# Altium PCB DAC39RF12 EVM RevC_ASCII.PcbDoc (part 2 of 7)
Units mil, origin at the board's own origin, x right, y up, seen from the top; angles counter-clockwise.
Board outline 5071.81 x 2716.54 mil, 16 copper layers (Top Layer, L2 GND1, L3 PWR1, L4 GND2, L5 PWR2, L6 GND3, L7 Ctrl Signal 1, L8 GND4, L9 GND5, L10 Ctrl Signal 2, L11 GND6, L12 PWR3, L13 GND7, L14 PWR4, L15 GND8, Bottom Layer), stack 82.4 mil thick; 596 components, 375 nets, 3310 pads, 1662 vias.
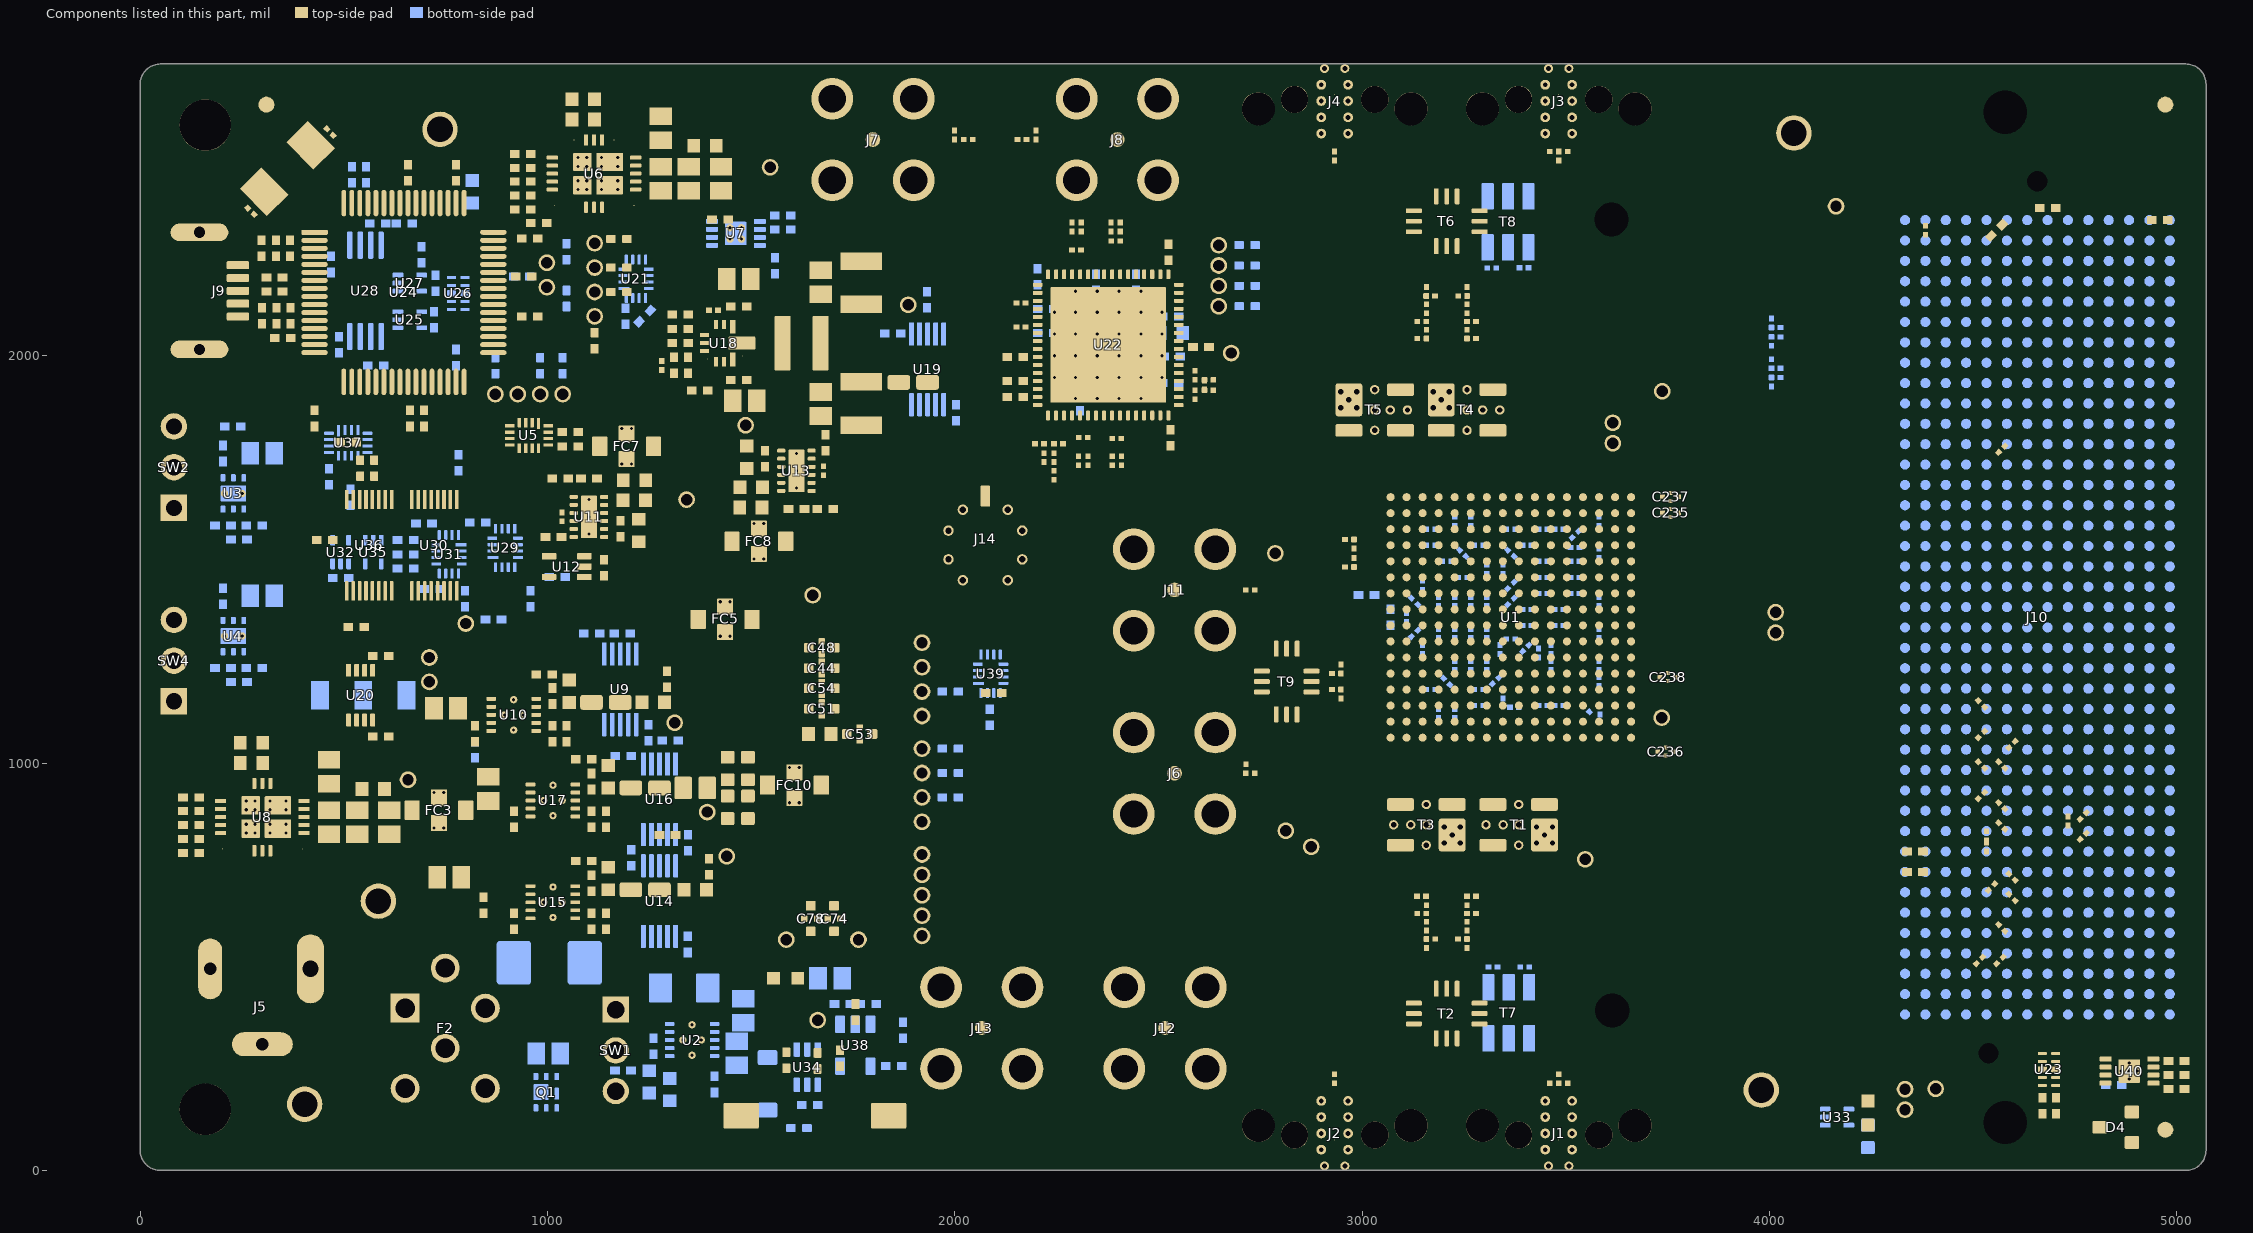
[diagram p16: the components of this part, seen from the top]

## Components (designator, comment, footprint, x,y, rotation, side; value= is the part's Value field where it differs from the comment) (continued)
C65 "C1005X5R1A225K050BC" 0402L_cap 1533.96,1747.33 r270 top
C66 "GRM033R61A105ME44D" 0201_cap#1 1677.76,1717.81 r270 top
C67 "0603ZD106KAT2A" 0603L_cap#1 1499.51,1627.77 r0 top
C68 "GRM155R61E104KA87D" 0402L#1 1423.77,2334.95 r180 top
C69 "GRM155R61E104KA87D" 0402L#1 1191.41,2097.15 r90 bottom
C70 "GRM155R61E104KA87D" 0402L#1 1238.85,2097.29 r45 bottom
C71 "0603ZD106KAT2A" 0603L_cap#1 1500.49,1677.45 r0 top
C72 "GRM155R61E104KA87D" 0402L#1 1344.42,554.91 r270 bottom
C73 "GRM155R61E104KA87D" 0402L#1 4703.69,159.33 r270 top
C74 "NFM18PC105R0J3D" NFM18PC 1703.55,618.42 r270 top
C75 "0603ZD106KAT2A" 0603L_cap#1 1149.61,716.77 r270 top
C76 "C1005X5R1E105K050BC" 0402L_cap 1396.1,745.89 r270 top
C77 "GRM033Z71C104KE14D" 0201_cap#3 2623.73,1915.48 r180 top
C78 "NFM18PC105R0J3D" NFM18PC 1646.35,618.42 r270 top
C79 "C1005X5R1A475K050BE" 0402L_cap 1143.61,612.01 r90 top
C80 "GRM155R61E104KA87D" 0402L#1 1344.45,804.91 r270 bottom
C81 "GRM033Z71C104KE14D" 0201_cap#3 2623.73,1941.17 r180 top
C82 "0603ZD106KAT2A" 0603L_cap#1 1149.61,966.77 r270 top
C83 "GRM188R60J476ME15D" 0603L_cap#2 1442.17,986.77 r270 top
C84 "GRM155R61E104KA87D" 0402L#1 2085.82,1112.49 r90 bottom
C85 "C1005X5R1A475K050BE" 0402L_cap 1143.61,862.01 r90 top
C86 "08053D106KAT4A" 0805L_cap 1469.78,2188.58 r180 top
C87 "08053D106KAT4A" 0805L_cap 1484.62,1889.53 r180 top
C88 "04023D104KAT2A" 0402L_cap 1469.78,2121.53 r180 top
C89 "04023D104KAT2A" 0402L_cap 1469.78,1940.83 r180 top
C90 "GRM033Z71C104KE14D" 0201_cap#1 1407.65,2111.94 r180 top
C91 "C2012X7S1A226M125AC" 0805L_cap 1670.46,1881.65 r90 top
C92 "C2012X7S1A226M125AC" 0805L_cap 1670.46,2180.71 r270 top
C93 "1210YD476KAT2A" 1210L_cap 1770.46,2179.33 r270 top
C94 "1210YD476KAT2A" 1210L_cap 1770.46,1883.03 r90 top
C95 "GRM155R61E104KA87D" 0402L#1 2002.44,1860.49 r270 bottom
C96 "C1005X5R1A225K050BC" 0402L_cap 1373.99,1915.42 r0 top
C97 "GRM155R61E104KA87D" 0402L#1 1055.77,1812.47 r180 top
C98 "GRM155R61E104KA87D" 0402L#1 1055.77,1777.47 r180 top
C99 "0201BB104KW160" 0201_cap#1 2725.49,975.31 r180 top
C100 "0201BB104KW160" 0201_cap#1 2947.76,1169.6 r90 top
C101 "0201BB104KW160" 0201_cap#1 2714.47,986.33 r270 top
C102 "0201BB104KW160" 0201_cap#1 2936.74,1180.62 r180 top
C103 "0201BB104KW160" 0201_cap#1 2936.74,1219.99 r180 top
C104 "0201BB104KW160" 0201_cap#1 2947.76,1231.02 r270 top
C105 "0201BB104KW160" 0201_cap#1 2725.49,1425.31 r180 top
C106 "GRM033Z71C104KE14D" 0201_cap#1 2219.07,1750.05 r90 top
C107 "GRM033Z71C104KE14D" 0201_cap#1 2243.6,1750.05 r90 top
C108 "GRM155R61E104KA87D" 0402L#1 2095.82,1172.18 r0 top
C109 "GRM188R60J476ME15D" 0603L_cap#2 1442.17,891.65 r90 top
C110 "GRM188R60J476ME15D" 0603L_cap#2 1492.17,986.77 r270 top
C111 "GRM188R60J476ME15D" 0603L_cap#2 1492.17,891.65 r90 top
C115 "GRM155R61E104KA87D" 0402L#1 2524.11,2254.66 r270 top
C116 "GRM155R61E104KA87D" 0402L#1 2445.37,2180.29 r90 bottom
C117 "GRM155R61E104KA87D" 0402L#1 2346.95,2180.29 r90 bottom
C118 "GRM155R61E104KA87D" 0402L#1 2203.25,2194.07 r270 bottom
C119 "GRM155R61E104KA87D" 0402L#1 2222.93,2115.33 r180 bottom
C120 "GRM155R61E104KA87D" 0402L#1 2222.93,2056.28 r180 bottom
C121 "GRM155R61E104KA87D" 0402L#1 2148.56,1997.22 r0 top
C122 "GRM155R61E104KA87D" 0402L#1 2148.56,1938.17 r0 top
C123 "GRM155R61E104KA87D" 0402L#1 2148.56,1898.8 r0 top
C124 "GRM155R61E104KA87D" 0402L#1 2307.58,1885.02 r270 bottom
C125 "GRM155R61E104KA87D" 0402L#1 2529.03,1798.84 r90 top
C126 "GRM155R61E104KA87D" 0402L#1 2604.39,2021.28 r180 top
C127 "GRM033Z71C104KE14D" 0201_cap#1 2162.22,2070.96 r0 top
C128 "GRM033Z71C104KE14D" 0201_cap#1 2162.22,2130.02 r0 top
C131 "GRM033Z71C104KE14D" 0201_cap#1 2406.14,2316 r270 top
C132 "GRM033Z71C104KE14D" 0201_cap#1 2383.19,2316 r270 top
C133 "GRM033Z71C104KE14D" 0201_cap#1 2310.47,2316 r270 top
C134 "GRM033Z71C104KE14D" 0201_cap#1 2287.29,2316 r270 top
C137 "GRM033Z71C104KE14D" 0201_cap#1 2303.91,1742.5 r90 top
C138 "GRM033Z71C104KE14D" 0201_cap#1 2326.87,1742.5 r90 top
C139 "GRM033Z71C104KE14D" 0201_cap#1 2386.71,1742.5 r90 top
C140 "GRM033Z71C104KE14D" 0201_cap#1 2409.66,1742.5 r90 top
C144 "C1608X5R1A106K080AC" 0603L_cap#1 2532.14,2055.96 r0 bottom
C145 "GRM155R61E104KA87D" 0402L#1 2530.02,2096.65 r0 bottom
C146 "04026D475KAT2A" 0402L_cap 369.53,2098.23 r90 top
C147 "04023D104KAT2A" 0402L_cap 334.53,2098.23 r90 top
C148 "04023D104KAT2A" 0402L_cap 657.49,2449.65 r270 top
C149 "04023D104KAT2A" 0402L_cap 775.6,2449.65 r270 top
C150 "04023D104KAT2A" 0402L_cap 578.75,1975.99 r180 bottom
C151 "04023D104KAT2A" 0402L_cap 936.82,2195.01 r180 bottom
C152 "04023D104KAT2A" 0402L_cap 775.6,1995.68 r270 bottom
C153 "04026D475KAT2A" 0402L_cap 368.16,2263.75 r270 top
C154 "04023D104KAT2A" 0402L_cap 333.16,2263.75 r270 top
C155 "GRM155R61E104KA87D" 0402L#1 941.82,2195.01 r0 top
C158 "04023D104KAT2A" 0402L_cap 487.77,2027.53 r90 bottom
C159 "GJM0336C1E180JB01J" 0201_cap#1 272.06,2355.03 r135 top
C160 "GJM0336C1E180JB01J" 0201_cap#1 466.2,2549.17 r135 top
C161 "GRM155R61E104KA87D" 0402L#1 958.05,1403.19 r270 bottom
C162 "GRM155R61E104KA87D" 0402L#1 867.57,1353.03 r0 bottom
C163 "GRM155R61E104KA87D" 0402L#1 798.05,1403.19 r90 bottom
C164 "GRM155R61E104KA87D" 0402L#1 829.24,1590.72 r0 bottom
C165 "GRM155R61E104KA87D" 0402L#1 696.86,1588.38 r0 bottom
C167 "GRM155R61E104KA87D" 0402L#1 516.29,1652.55 r90 bottom
C168 "GRM155R61E104KA87D" 0402L#1 511.13,1787.79 r0 top
C169 "GRM155R61E104KA87D" 0402L#1 463.71,1703.11 r90 bottom
C170 "GRM155R61E104KA87D" 0402L#1 1755.73,388.93 r90 top
C171 "GRM155R61E104KA87D" 0402L#1 1718.33,275.94 r270 top
C172 "GRM033Z71C104KE14D" 0201_cap#1 3109.18,1357.79 r270 bottom
C173 "GRM033Z71C104KE14D" 0201_cap#1 3373.74,1137.25 r0 bottom
C174 "GRM033Z71C104KE14D" 0201_cap#1 3550.04,1133.46 r135 bottom
C175 "GRM033Z71C104KE14D" 0201_cap#1 3432.74,1270.39 r270 bottom
C176 "GRM033Z71C104KE14D" 0201_cap#1 3463.51,1279.05 r90 bottom
C177 "GRM033Z71C104KE14D" 0201_cap#1 3404.45,1377.47 r0 bottom
C178 "GRM033Z71C104KE14D" 0201_cap#1 3443.82,1495.58 r0 bottom
C179 "GRM033Z71C104KE14D" 0201_cap#1 3345.4,1475.9 r270 bottom
C180 "GRM033Z71C104KE14D" 0201_cap#1 3581.62,1515.27 r90 bottom
C181 "GRM033Z71C104KE14D" 0201_cap#1 3523.45,1561.53 r45 bottom
C182 "GRM033Z71C104KE14D" 0201_cap#1 3443.82,1574.32 r180 bottom
C183 "GRM033Z71C104KE14D" 0201_cap#1 3338.4,1279.05 r270 bottom
C184 "GRM033Z71C104KE14D" 0201_cap#1 3365.08,1304.73 r0 bottom
C185 "GRM033Z71C104KE14D" 0201_cap#1 3483.19,1377.47 r0 bottom
C186 "GRM033Z71C104KE14D" 0201_cap#1 3443.82,1416.84 r0 bottom
C187 "GRM033Z71C104KE14D" 0201_cap#1 3365.08,1397.16 r45 bottom
C188 "GRM033Z71C104KE14D" 0201_cap#1 3365.08,1515.27 r315 bottom
C189 "GRM033Z71C104KE14D" 0201_cap#1 3581.62,1318.42 r270 bottom
C190 "GRM033Z71C104KE14D" 0201_cap#1 3581.62,1239.68 r90 bottom
C191 "GRM033Z71C104KE14D" 0201_cap#1 3483.19,1141.25 r0 bottom
C192 "GRM033Z71C104KE14D" 0201_cap#1 3581.62,1397.16 r90 bottom
C193 "GRM033Z71C104KE14D" 0201_cap#1 3443.82,1141.25 r180 bottom
C194 "GRM033Z71C104KE14D" 0201_cap#1 3583.62,1130.23 r90 bottom
C195 "GRM033Z71C104KE14D" 0201_cap#1 3581.62,1200.31 r270 bottom
C196 "GRM033Z71C104KE14D" 0201_cap#1 3168.23,1574.32 r180 bottom
C197 "GRM033Z71C104KE14D" 0201_cap#1 3168.23,1534.95 r180 bottom
C198 "GRM033Z71C104KE14D" 0201_cap#1 3246.97,1515.27 r315 bottom
C199 "GRM033Z71C104KE14D" 0201_cap#1 3286.34,1534.95 r0 bottom
C200 "GRM033Z71C104KE14D" 0201_cap#1 3266.66,1594.01 r90 bottom
C201 "GRM033Z71C104KE14D" 0201_cap#1 3227.29,1594.01 r90 bottom
C202 "GRM033Z71C104KE14D" 0201_cap#1 3227.29,1239.68 r270 bottom
C203 "GRM033Z71C104KE14D" 0201_cap#1 3266.66,1239.68 r90 bottom
C204 "GRM033Z71C104KE14D" 0201_cap#1 3266.66,1318.42 r90 bottom
C205 "GRM033Z71C104KE14D" 0201_cap#1 3266.66,1397.16 r270 bottom
C206 "GRM033Z71C104KE14D" 0201_cap#1 3246.97,1456.21 r0 bottom
C207 "GRM033Z71C104KE14D" 0201_cap#1 3207.6,1495.58 r0 bottom
C208 "GRM033Z71C104KE14D" 0201_cap#1 3227.29,1318.42 r90 bottom
C209 "GRM033Z71C104KE14D" 0201_cap#1 3187.92,1318.42 r90 bottom
C210 "GRM033Z71C104KE14D" 0201_cap#1 3401.56,1282.16 r225 bottom
C211 "GRM033Z71C104KE14D" 0201_cap#1 3404.45,1338.1 r0 bottom
C212 "GRM033Z71C104KE14D" 0201_cap#1 3483.19,1338.1 r0 bottom
C213 "GRM033Z71C104KE14D" 0201_cap#1 3443.82,1456.21 r180 bottom
C214 "GRM033Z71C104KE14D" 0201_cap#1 3365.08,1436.53 r45 bottom
C215 "GRM033Z71C104KE14D" 0201_cap#1 3404.45,1534.95 r0 bottom
C216 "GRM033Z71C104KE14D" 0201_cap#1 3581.62,1594.01 r270 bottom
C217 "GRM033Z71C104KE14D" 0201_cap#1 3483.19,1574.32 r0 bottom
C218 "GRM033Z71C104KE14D" 0201_cap#1 3365.08,1574.32 r0 bottom
C219 "GRM033Z71C104KE14D" 0201_cap#1 3187.92,1121.57 r270 bottom
C220 "GRM033Z71C104KE14D" 0201_cap#1 3207.6,1200.31 r135 bottom
C221 "GRM033Z71C104KE14D" 0201_cap#1 3168.23,1180.62 r180 bottom
C222 "GRM033Z71C104KE14D" 0201_cap#1 3227.29,1121.57 r270 bottom
C223 "GRM033Z71C104KE14D" 0201_cap#1 3286.34,1141.25 r0 bottom
C224 "GRM033Z71C104KE14D" 0201_cap#1 3286.34,1180.62 r0 bottom
C225 "GRM033Z71C104KE14D" 0201_cap#1 3306.03,1239.68 r90 bottom
C226 "GRM033Z71C104KE14D" 0201_cap#1 3306.03,1318.42 r90 bottom
C227 "GRM033Z71C104KE14D" 0201_cap#1 3306.03,1397.16 r270 bottom
C228 "GRM033Z71C104KE14D" 0201_cap#1 3306.03,1475.9 r270 bottom
C229 "GRM033Z71C104KE14D" 0201_cap#1 3227.29,1397.16 r270 bottom
C230 "GRM033Z71C104KE14D" 0201_cap#1 3187.92,1397.16 r270 bottom
C231 "GRM033Z71C104KE14D" 0201_cap#1 3148.55,1279.05 r90 bottom
C232 "GRM033Z71C104KE14D" 0201_cap#1 3128.86,1318.42 r45 bottom
C233 "GRM033Z71C104KE14D" 0201_cap#1 3128.86,1397.16 r315 bottom
C234 "GRM033Z71C104KE14D" 0201_cap#1 3148.55,1436.53 r270 bottom
C235 "NFM15PC474R0J3D" NFM15PC 3757.18,1614.22 r180 top
C236 "NFM15PC474R0J3D" NFM15PC 3745.31,1028.04 r180 top
C237 "NFM15PC474R0J3D" NFM15PC 3757.18,1653.9 r180 top
C238 "NFM15PC474R0J3D" NFM15PC 3750.61,1211.1 r180 top
C239 "GRM033Z71C104KE14D" 0201_cap#1 3345.4,1169.6 r90 bottom
C240 "GRM033Z71C104KE14D" 0201_cap#1 3327.71,1202.31 r45 bottom
C241 "GRM033Z71C104KE14D" 0201_cap#1 3522.56,1495.58 r0 bottom
C242 "GRM033Z71C104KE14D" 0201_cap#1 3522.56,1416.84 r0 bottom
C243 "GRM033Z71C104KE14D" 0201_cap#1 3522.56,1456.21 r0 bottom
C244 "GRM033Z71C104KE14D" 0201_cap#1 3522.56,1529.45 r0 bottom
C245 "GRM155R61E104KA87D" 0402L#1 4844.92,209.51 r180 bottom
D1 "MBR130T1G" SOD-123 1540.24,212.76 r270 bottom
D2 "SMBJ15CA" SMBJ15CA 1004.55,510 r0 bottom
D3 "LTST-C191TGKT" LED_LTST-C190-Green 1584.78,471.85 r0 top
D4 "SDM40E20LC-7" SOT-323-DIO 4850.34,106.08 r180 top
D5 "LTST-C191TGKT" LED_LTST-C190-Green 4241.78,140.84 r90 top
F1 "SF-1206FP250-2" SF-1206F500M-2_1206 1335.43,448.25 r180 bottom
F2 "BNX002-11" FIL_BNX002-11 749.06,300.06 r90 top
FB1 "BLE18PS080SN1D" 0603L#1 1386.69,2516.13 r0 top
FB2 "BLE18PS080SN1D" 0603L#1 572.33,936.49 r0 top
FB3 "BLE18PS080SN1D" 0603L#1 1259.67,1149.17 r0 top
FB4 "BLE18PS080SN1D" 0603L#1 1668.65,1071.46 r0 top
FB5 "BLE18PS080SN1D" 0603L#1 1362.64,689.21 r0 top
FB6 "BLM21SP471SN1D" 0805L#1 1362.64,939.21 r0 top
FB7 "NFZ15SG151SN11D" 0402L#1 299.53,2098.23 r90 top
FB8 "NFZ15SG151SN11D" 0402L#1 298.16,2263.75 r270 top
FC3 "FeedThruCap" NFM31PC#1 733.64,884.41 r0 top
FC5 "FeedThruCap" NFM31PC#2 1436.08,1352.91 r0 top
FC7 "FeedThruCap" NFM31PC#1 1194.46,1777.79 r0 top
FC8 "FeedThruCap" NFM31PC#1 1518.84,1544.65 r180 top
FC10 "FeedThruCap" NFM31PC#1 1606.14,946.1 r0 top
FID1 "Fiducial Mark" Fiducial10-20 4971.81,100 r0 top
FID2 "Fiducial Mark" Fiducial10-20 4971.81,2616.54 r90 top
FID3 "Fiducial Mark" Fiducial10-20 310,2616.54 r90 top
H3 "2069-440-SS" FP-2116-440-AL_STANDOFF_HEX_1-4-MFG 160,2566.54 r0 top locked
H4 "2069-440-SS" FP-2116-440-AL_STANDOFF_HEX_1-4-MFG 160,150 r0 top
H5 "Balun-Shield" Balun-Shield 3360,386.83 r180 bottom
H6 "Balun-Shield" Balun-Shield 3358.16,2328.74 r180 bottom
J1 "HK-LR-SR2(11)" HiRose-HK-LR-SR2-SWM1092-04A-MicroStirp-6mil-Female-Backdrill 3482.6,0 r90 top
J2 "HK-LR-SR2(11)" HiRose-HK-LR-SR2-SWM1092-04A-MicroStirp-6mil-Female-Backdrill 2932.6,0 r90 top
J3 "HK-LR-SR2(11)" HiRose-HK-LR-SR2-SWM1092-04A-MicroStirp-6mil-Female-Backdrill 3482.6,2716.53 r270 top
J4 "HK-LR-SR2(11)" HiRose-HK-LR-SR2-SWM1092-04A-MicroStirp-6mil-Female-Backdrill 2932.6,2716.53 r270 top
J5 "RAPC722X" RAPC722X -140.83,495.04 r0 top
J6 "132134-15" FP-132134-15_CONN_SMA_JACK-MFG#1 2539.47,975.31 r270 top
J7 "132134-15" FP-132134-15_CONN_SMA_JACK-MFG#1 1799.06,2530.98 r0 top
J8 "132134-15" FP-132134-15_CONN_SMA_JACK-MFG#1 2399.06,2530.98 r90 top
J9 "UX60SC-MB-5S8" Hirose_UX60SC-MB-5S8 0,2159.42 r0 top
J10 "ASP-184330-01" Samtec_ASP-184330-01 4657.81,1358.06 r90 top locked
J11 "132134-15" FP-132134-15_CONN_SMA_JACK-MFG#1 2539.47,1425.31 r270 top
J12 "132134-15" FP-132134-15_CONN_SMA_JACK-MFG#2 2516.35,349.76 r90 top
J13 "132134-15" FP-132134-15_CONN_SMA_JACK-MFG#2 2066.35,349.76 r90 top
J14 "0853050232" Molex_0853050232 2075,1655.63 r0 top
L1 "XGL4020-152MEC" XGL4020 1623.81,2031.18 r0 top
LBL1 "THT-14-423-10" Label_650x200 4915.43,1876.87 r90 top
Logo1 "FDL Logo" FDL_Small 1192.35,1313.11 r0 top
LOGO2 "CAUTION HOT SURFACE" IEC_HotSurface_Small 3490,1815 r0 top
Logo3 "FCC disclaimer" FCC_disclaimer_stacked 4325,2325 r90 bottom
Logo4 "ESD Overlay" ESD_Overlay_Small 3785,1355 r0 top
Logo5 "WEEE" WEEE_Minimum 2810,1755 r180 bottom
LOGO6 "CE Mark" CE_Mark_5mm 2930,2430 r180 bottom
Logo7 "Texas Instruments" TI_Stacked_Overlay_Small 4205,2168.58 r0 top
MP1 "ATS-54170R-C1-R0" "DAC39 - ATS-54170R-C1-R0_BGA_HEATSINK_17p0x17p0mm" 3365.08,1357.79 r90 top
MP5 "Fan" "DAC39R - F17HA-05HC_FAN_17p0x17p0mm" 3700.08,1357.79 r0 top
PP1 "Probe Point" ProbePoint_TH_40mil 4015,1320.51 r0 top
PP2 "Probe Point" ProbePoint_TH_40mil 4015,1370.51 r0 top
PP3 "Probe Point" ProbePoint_TH_40mil 1546.48,2462.66 r0 top
PP4 "Probe Point" ProbePoint_TH_40mil 657.7,959.41 r0 top
PP5 "Probe Point" ProbePoint_TH_40mil 1312.22,1099.17 r0 top
PP6 "Probe Point" ProbePoint_TH_40mil 2812.76,834.2 r0 top
PP7 "Probe Point" ProbePoint_TH_40mil 3615.6,1835.45 r0 top
PP8 "Probe Point" ProbePoint_TH_40mil 3735.49,1111.72 r0 top
PP9 "Probe Point" ProbePoint_TH_40mil 2787.07,1514.97 r0 top
PP10 "Probe Point" ProbePoint_TH_40mil 3615.6,1785.45 r0 top
PP11 "Probe Point" ProbePoint_TH_40mil 1486.35,1829.37 r90 top
PP12 "Probe Point" ProbePoint_TH_40mil 1341.46,1647.14 r90 top
PP13 "Probe Point" ProbePoint_TH_40mil 1440.2,771.1 r0 top
PP14 "Probe Point" ProbePoint_TH_40mil 1763.55,566.92 r0 top
PP15 "Probe Point" ProbePoint_TH_40mil 1586.35,566.92 r0 top
PP16 "Probe Point" ProbePoint_TH_40mil 1392.16,880 r90 top
PP17 "Probe Point" ProbePoint_TH_40mil 1885.57,2125.06 r0 top
PP18 "Probe Point" ProbePoint_TH_40mil 2678.46,2006.82 r90 top
PP19 "Probe Point" ProbePoint_TH_40mil 998.74,2168.58 r90 top
PP20 "Probe Point" ProbePoint_TH_40mil 998.74,2228.58 r90 top
PP21 "Probe Point" ProbePoint_TH_40mil 2647.94,2221.79 r0 top
PP22 "Probe Point" ProbePoint_TH_40mil 2647.94,2171.79 r0 top
PP23 "Probe Point" ProbePoint_TH_40mil 2647.94,2121.79 r0 top
PP24 "Probe Point" ProbePoint_TH_40mil 2647.94,2271.79 r0 top
PP25 "Probe Point" ProbePoint_TH_40mil 1919.48,1175.8 r0 top
PP26 "Probe Point" ProbePoint_TH_40mil 1919.48,775.8 r90 top
PP27 "Probe Point" ProbePoint_TH_40mil 1919.48,675.8 r0 top
PP28 "Probe Point" ProbePoint_TH_40mil 1919.48,575.8 r0 top
PP29 "Probe Point" ProbePoint_TH_40mil 1919.48,725.8 r0 top
PP30 "Probe Point" ProbePoint_TH_40mil 1919.48,1235.8 r0 top
PP31 "Probe Point" ProbePoint_TH_40mil 1919.48,625.8 r90 top
PP32 "Probe Point" ProbePoint_TH_40mil 799.59,1342.79 r0 top
PP33 "Probe Point" ProbePoint_TH_40mil 1919.48,1115.8 r0 top
PP34 "Probe Point" ProbePoint_TH_40mil 1919.48,1295.8 r0 top
PP35 "Probe Point" ProbePoint_TH_40mil 1651.17,1412.58 r0 top
PP36 "Probe Point" ProbePoint_TH_40mil 1919.48,1035.8 r270 top
PP37 "Probe Point" ProbePoint_TH_40mil 1919.48,975.8 r270 top
PP38 "Probe Point" ProbePoint_TH_40mil 1919.48,915.8 r0 top
PP39 "Probe Point" ProbePoint_TH_40mil 1919.48,855.8 r0 top
PP40 "Probe Point" ProbePoint_TH_40mil 1663.3,369.24 r90 top
PP41 "Probe Point" ProbePoint_TH_40mil 3547.64,763.72 r90 top
PP42 "Probe Point" ProbePoint_TH_40mil 3736.83,1913.06 r90 top
PP43 "Probe Point" ProbePoint_TH_40mil 2874.85,794.47 r0 top
PP44 "Probe Point" ProbePoint_TH_40mil 1037.24,1906.09 r90 top
PP45 "Probe Point" ProbePoint_TH_40mil 982.24,1906.09 r90 top
PP46 "Probe Point" ProbePoint_TH_40mil 927.24,1906.09 r90 top
PP47 "Probe Point" ProbePoint_TH_40mil 872.24,1906.09 r90 top
PP48 "Probe Point" ProbePoint_TH_40mil 4332.81,199.51 r0 top
PP49 "Probe Point" ProbePoint_TH_40mil 4332.81,149.51 r0 top
PP50 "Probe Point" ProbePoint_TH_40mil 4163.4,2367.25 r0 top
PP51 "Probe Point" ProbePoint_TH_40mil 4407.81,200.66 r90 top
PP52 "Probe Point" ProbePoint_TH_40mil 710.18,1259.36 r0 top
PP53 "Probe Point" ProbePoint_TH_40mil 710.18,1199.36 r0 top
PP54 "Probe Point" ProbePoint_TH_40mil 1115.72,2096.71 r180 top
PP55 "Probe Point" ProbePoint_TH_40mil 1115.72,2156.71 r180 top
PP56 "Probe Point" ProbePoint_TH_40mil 1115.72,2216.71 r180 top
PP57 "Probe Point" ProbePoint_TH_40mil 1115.72,2276.71 r180 top
Q1 "CSD15571Q2" DQK0006C 997.2,192.2 r270 bottom
R1 "ERJ-1GN0R00C" 0201#1 3268.63,673.35 r0 top
R2 "ERJ-1GN0R00C" 0201#1 3482.6,225.06 r90 top
R3 "ERJ-1GN0R00C" 0201#1 3257.61,662.33 r270 top
R4 "ERJ-1GN0R00C" 0201#1 3257.61,599.88 r270 top
R5 "ERJ-1GN0R00C" 0201#1 3157.6,662.33 r270 top
R6 "ERJ-1GN0R00C" 0201#1 3157.6,599.88 r270 top
R7 "ERJ-1GNF1400C" 0201#1 3146.57,631.1 r0 top
R8 "ERJ-1GNF1400C" 0201#1 3268.63,631.1 r180 top
R9 "ERJ-1GN0R00C" 0201#1 3145.79,673.35 r180 top
R10 "ERJ-1GN0R00C" 0201#1 2932.6,225.06 r270 top
R11 "ERJ-1GN0R00C" 0201#1 3268.63,2042.22 r0 top
R12 "ERJ-1GN0R00C" 0201#1 3482.6,2490.51 r270 top
R13 "ERJ-1GN0R00C" 0201#1 3257.61,2053.25 r90 top
R14 "ERJ-1GN0R00C" 0201#1 3257.61,2115.7 r90 top
R15 "ERJ-1GN0R00C" 0201#1 3157.6,2053.25 r90 top
R16 "ERJ-1GN0R00C" 0201#1 3157.6,2115.7 r90 top
R17 "ERJ-1GNF1400C" 0201#1 3146.57,2084.47 r0 top
R18 "ERJ-1GNF1400C" 0201#1 3268.63,2084.47 r180 top
R19 "ERJ-1GN0R00C" 0201#1 3146.57,2042.22 r180 top
R20 "ERJ-1GN0R00C" 0201#1 2932.6,2490.51 r90 top
R21 "ERJ-2RKF1004X" 0402L#1 1260,304.77 r90 bottom
R22 "ERJ-2RKF4532X" 0402L#1 1410.24,211.26 r90 bottom
R23 "ERJ-2RKF1623X" 0402L#1 1185.43,245 r0 bottom
R24 "ERJ-6ENF4871V" 0805L#2 1693.84,471.85 r180 bottom
R25 "RCA12060000ZSEA" 1206L 494.59,1166.72 r180 bottom
R26 "RCA12060000ZSEA" 1206L 600.88,1166.72 r0 bottom
R27 "ERJ-2RKF1002X" 0402L#1 716.7,1428.1 r180 bottom
R28 "ERJ-2RKF1002X" 0402L#1 203.38,1760.11 r90 bottom
R29 "ERJ-U02F2002X" 0402L#1 242.75,1548.65 r0 bottom
R30 "ERJ-2RKF1002X" 0402L#1 203.38,1410.11 r90 bottom
R31 "ERJ-U02F3602X" 0402L#1 242.75,1198.65 r0 bottom
R32 "ERJ-2RKF1202X" 0402L#1 203.38,1583.65 r0 bottom
R33 "ERJ-2RKF1202X" 0402L#1 203.38,1233.65 r0 bottom
R34 "ERJ-1GNF49R9C" 0201#2 1998.94,2542 r270 top
R35 "ERJ-U01J561C" 0201#1 2612.7,1928.32 r90 top
R36 "ERJ-2RKF1002X" 0402L#1 939.44,2359.63 r180 top
R37 "ERJ-1GNF2400C" 0201#1 2208.05,1784.07 r0 top
R38 "ERJ-1GNF2400C" 0201#1 2254.62,1784.07 r180 top
R39 "ERA-2AEB1542X" 0402L#1 939.44,2461.63 r180 top
R40 "ERJ-2RKF1002X" 0402L#1 978.81,2325.63 r180 top
R41 "ERJ-2RKF4222X" 0402L#1 939.44,2393.63 r0 top
R42 "ERJ-2RKF4871X" 0402L#1 939.44,2427.63 r0 top
R43 "ERJ-1GNF49R9C" 0201#2 2199.06,2542 r270 top
R44 "ERJ-2RKF49R9X" 0402L#1 956.82,2096.27 r0 top
R45 "ERJ-2RKF1002X" 0402L#1 1558.34,2220.9 r270 bottom
R46 "ERJ-2RKF1002X" 0402L#1 821.87,1032.64 r90 bottom
R47 "ERJ-2RKF1002X" 0402L#1 125.08,779.98 r180 top
R48 "ERJ-2RKF9311X" 0402L#1 125.08,881.98 r180 top
R49 "ERJ-2RKF4222X" 0402L#1 125.08,813.98 r0 top
R50 "ERJ-2RKF4871X" 0402L#1 125.08,847.98 r0 top
R51 "ERJ-2GE0R00X" 0402L#1 1183.97,1317.79 r180 bottom
R52 "ERJ-2GE0R00X" 0402L#1 1108.62,1317.79 r0 bottom
R53 "ERJ-H2RF1002X" 0402L#1 821.87,1072.01 r270 top
R54 "CSS0603FT5L00" CCS0603FLxLxx 1143.54,1149.17 r0 top
R55 "ERJ-2RKF8872X" 0402L#1 1012.11,1164.92 r270 top
R56 "ERJ-U2RD1202X" 0402L#1 1012.11,1072.01 r90 top
R57 "ERJ-2RKF1242X" 0402L#1 992.42,1217.64 r0 top
R58 "ERJ-2RKF1002X" 0402L#1 1139.34,1480.11 r270 top
R59 "ERJ-2RKF2552X" 0402L#1 1101.94,1698.85 r0 top
R60 "ERJ-2RKF1002X" 0402L#1 1014.85,1555.42 r0 top
R61 "ERJ-2RKF4992X" 0402L#1 1031.57,1698.85 r0 top
R62 "ERA-2AED101X" 0402L#1 691.13,2247.94 r90 bottom
R63 "ERJ-2RKF1002X" 0402L#1 1578.02,2344.95 r180 bottom
R64 "ERJ-2RKF2552X" 0402L#1 1611.36,1623.59 r180 top
R65 "ERJ-2RKF1002X" 0402L#1 1682.76,1786.7 r270 top
R66 "ERJ-2RKF4992X" 0402L#1 1681.73,1623.59 r180 top
R67 "ERJ-2GE0R00X" 0402L#1 1294.76,823.96 r180 top
R68 "ERJ-2GE0R00X" 0402L#1 1205.71,767.51 r270 bottom
R69 "ERJ-H2RF1002X" 0402L#1 918.37,612.01 r270 top
R70 "ERJ-2RKF1002X" 0402L#1 843.53,651.38 r90 top
R71 "CSS0603FT5L00" CCS0603FLxLxx 1240.04,689.21 r0 top
R72 "ERJ-2RKF1153X" 0402L#1 1108.61,704.92 r270 top
R73 "ERJ-2RKF6651X" 0402L#1 1108.61,612.01 r90 top
R74 "ERJ-2RKF3302X" 0402L#1 1088.92,759.61 r0 top
R75 "ERJ-2GE0R00X" 0402L#1 1301.63,1055.19 r180 bottom
R76 "ERJ-2GE0R00X" 0402L#1 1186.02,1017.82 r0 bottom
R77 "ERJ-H2RF1002X" 0402L#1 918.37,862.01 r270 top
R78 "ERJ-2RKF1002X" 0402L#1 1578.02,2310.27 r180 bottom
R79 "CSS0603FT5L00" CCS0603FLxLxx 1240.04,939.21 r0 top
R80 "ERJ-2RKF1153X" 0402L#1 1108.61,954.92 r270 top
R81 "ERJ-2RKF6651X" 0402L#1 1108.61,862.01 r90 top
R82 "ERJ-2RKF3302X" 0402L#1 1088.92,1009.61 r0 top
R83 "ERJ-2RKF1002X" 0402L#1 1325.94,2031.18 r180 top
R84 "CSS0603FT2L00" CCS0603FLxLxx 1897.64,1934.79 r180 top
R85 "ERJ-2GE0R00X" 0402L#1 1931.2,2137.29 r270 bottom
R86 "ERJ-2GE0R00X" 0402L#1 1847.51,2054.58 r0 bottom
R87 "ERJ-H2RF1002X" 0402L#1 1310.62,1976.49 r270 top
R88 "ERJ-2RKF4871X" 0402L#1 1325.94,2066.18 r0 top
R89 "ERJ-2RKF1742X" 0402L#1 1325.94,2101.18 r0 top
R90 "ERJ-H2RF1002X" 0402L#1 1344.62,1976.49 r90 top
R91 "ERJ-1GNF49R9C" 0201#1 2243.6,1707 r90 top
R92 "ERJ-1GN0R00C" 0201#1 4016.02,1969.56 r180 bottom
R93 "ERJ-1GN0R00C" 0201#1 4005,1980.58 r270 bottom
R94 "ERJ-1GN0R00C" 0201#1 4016.02,1946.56 r180 bottom
R95 "ERJ-2RKF1002X" 0402L#1 4669.81,159.33 r90 top
R96 "ERJ-1GN0R00C" 0201#1 4005,1935.53 r90 bottom
R97 "ERJ-1GN0R00C" 0201#1 4016.02,2069.56 r180 bottom
R98 "ERJ-1GN0R00C" 0201#1 4005,2080.58 r270 bottom
R99 "ERJ-1GN0R00C" 0201#1 4016.02,2046.56 r180 bottom
R100 "ERJ-1GN0R00C" 0201#1 4005,2035.53 r90 bottom
R101 "ERJ-U01J561C" 0201#1 2395.03,2281.98 r180 top
R102 "ERJ-U01J561C" 0201#1 2298.6,2259.43 r180 top
R103 "ERJ-1GNF2400C" 0201#3 2589.7,1904.46 r90 top
R104 "ERJ-1GNF2400C" 0201#3 2589.7,1952.19 r270 top
R105 "ERJ-U01J561C" 0201#1 2315.49,1799.07 r0 top
R106 "ERJ-U01J561C" 0201#1 2397.73,1796.62 r180 top
R107 "ERJ-1GN0R00C" 0201#1 2979.81,1492.74 r90 top
R108 "ERJ-1GN0R00C" 0201#1 2968.78,1481.72 r180 top
R109 "ERJ-1GN0R00C" 0201#1 2979.81,1537.79 r270 top
R110 "ERJ-1GN0R00C" 0201#1 2968.78,1548.82 r180 top
R111 "ERJ-2RKF1002X" 0402L#2 872.24,1975.77 r270 bottom
R112 "ERJ-H2RF1002X" 0402L#1 2529.96,1933.57 r0 bottom
R113 "ERJ-H2RF1002X" 0402L#1 2533.86,1998.26 r0 bottom
R114 "ERJ-2RKF49R9X" 0402L#1 428.16,1846.31 r270 top
R115 "ERJ-2RKF2201X" 0402L#1 662.86,1846.31 r90 top
R116 "ERJ-2RKF1002X" 0402L#1 721.13,2088.55 r90 bottom
R117 "ERJ-2RKF49R9X" 0402L#1 956.82,2288.12 r0 top
R118 "ERJ-2RKF1002X" 0402L#2 1046.4,2140.76 r270 bottom
R119 "ERJ-2RKF1002X" 0402L#2 1046.4,2255.87 r90 bottom
R120 "ERJ-2RKF1002X" 0402L#2 1989.17,1175.8 r180 bottom
R121 "ERJ-2RKF2201X" 0402L#1 696.86,1846.31 r90 top
R122 "ERJ-2RKF1002X" 0402L#1 725.13,2178.57 r90 bottom
R123 "ERJ-2GEJ100X" 0402L#1 349.84,2043.55 r180 top
R124 "ERJ-2GEJ100X" 0402L#1 329.84,2192.41 r0 top
R125 "ERJ-2GEJ100X" 0402L#1 329.84,2157.92 r0 top
R126 "ERJ-2GEJ123X" 0402L#1 468.16,2224.38 r270 bottom
R127 "ERJ-2GEJ103X" 0402L#1 554.38,2444.65 r90 bottom
R128 "ERJ-2GEJ103X" 0402L#1 648.13,2325.17 r0 bottom
R129 "ERJ-2GEJ103X" 0402L#1 519.69,2444.65 r90 bottom
R130 "ERJ-2GEJ222X" 0402L#1 583.76,2325.17 r180 bottom
R131 "ERJ-2RKF1002X" 0402L#2 982.24,1975.77 r270 bottom
R132 "ERJ-2RKF1002X" 0402L#2 1037.24,1975.77 r270 bottom
R133 "ERJ-2RKF1002X" 0402L#1 227.64,1826.62 r0 bottom
R134 "ERJ-2RKF49R9X" 0402L#1 781.78,1737.12 r270 bottom
R135 "ERJ-2RKF1002X" 0402L#1 492.25,1454.17 r0 bottom
R136 "ERJ-2RKF49R9X" 0402L#1 452.88,1547.44 r0 top
R137 "ERJ-2RKF49R9X" 0402L#1 651.62,1547.79 r180 bottom
R138 "ERJ-2RKF1002X" 0402L#2 1115.72,2037.03 r90 top
R139 "ERJ-2RKF1002X" 0402L#2 1175.4,2156.71 r180 top
R140 "ERJ-2RKF1002X" 0402L#1 651.62,1512.79 r0 bottom
R141 "ERJ-2RKF49R9X" 0402L#1 651.62,1477.79 r180 bottom
R142 "ERJ-2RKF49R9X" 0402L#1 530.42,1334.04 r0 top
R143 "ERJ-2GEJ104X" 0402L#1 1873.33,344.07 r90 bottom
R144 "ERJ-2RKF1002X" 0402L#1 1849.73,256.93 r180 bottom
R145 "ERJ-2GE0R00X" 0402L#1 1724.24,408.61 r180 bottom
R146 "ERJ-2GE0R00X" 0402L#1 1643.69,160.32 r180 bottom
R147 "ERJ-2GE0R00X" 0402L#1 1787.23,408.61 r0 bottom
R148 "ERJ-1GN0R00C" 0201#1 3463.51,1239.68 r270 bottom
R149 "ERJ-2RKF1001X" 0402L#1 3010.75,1412.79 r180 bottom
R150 "ERJ-2RKF3601X" 0402L#1 3069.81,1357.79 r90 bottom
R151 "ERJ-2GE0R00X" 0402L#1 4682.81,2363.06 r0 top
R152 "ERJ-1GN0R00C" 0201#1 4770.31,870.56 r45 top
R153 "ERJ-1GN0R00C" 0201#1 4732.81,858.06 r90 top
R154 "ERJ-1GN0R00C" 0201#1 4770.31,820.56 r45 top
R155 "ERJ-2GEJ101X" 0402L#1 4557.78,2308.02 r225 top
R156 "ERJ-1GN0R00C" 0201#1 4570.31,1770.56 r45 top
R157 "ERJ-2RKF1002X" 0402L#2 1175.4,2216.71 r180 top
R158 "ERJ-1GN0R00C" 0201#1 4520.31,1145.55 r315 top
R159 "ERJ-1GN0R00C" 0201#1 4520.31,1070.56 r45 top
R160 "ERJ-1GN0R00C" 0201#1 4520.31,995.56 r315 top
R161 "ERJ-1GN0R00C" 0201#1 4595.31,1045.56 r225 top
R162 "ERJ-1GN0R00C" 0201#1 4520.31,920.56 r45 top
R163 "ERJ-1GN0R00C" 0201#1 4570.31,995.56 r315 top
R164 "ERJ-1GN0R00C" 0201#1 4532.81,822.03 r90 top
R165 "ERJ-1GN0R00C" 0201#1 4570.31,895.56 r315 top
R166 "ERJ-1GN0R00C" 0201#1 4532.81,794.08 r270 top
R167 "ERJ-1GN0R00C" 0201#1 4570.31,845.56 r315 top
R168 "ERJ-1GN0R00C" 0201#1 4545.33,695.56 r225 top
R169 "ERJ-1GN0R00C" 0201#1 4595.31,720.56 r135 top
R170 "ERJ-2RKF1002X" 0402L#2 1175.4,2286.71 r180 top
R171 "ERJ-1GN0R00C" 0201#1 4595.31,670.56 r135 top
R172 "ERJ-1GN0R00C" 0201#1 4515.61,515.85 r45 top
R173 "ERJ-2RKF1002X" 0402L#1 4999.17,199.51 r180 top
R174 "ERJ-2RKF1002X" 0402L#1 4999.17,234.2 r180 top
R175 "ERJ-2RKF1002X" 0402L#1 4999.17,268.88 r180 top
R176 "ERJ-1GN0R00C" 0201#1 4570.31,595.56 r315 top
R177 "ERJ-1GN0R00C" 0201#1 4565.61,515.85 r45 top
R178 "ERJ-1GN0R00C" 0201#1 4382.81,2308.06 r90 top
R179 "ERJ-2GEJ101X" 0402L#1 4357.22,783.06 r0 top
R180 "ERJ-2GEJ101X" 0402L#1 4357.22,733.06 r0 top
R181 "ERJ-2GEJ101X" 0402L#1 4958.4,2333.06 r180 top
R182 "ERJ-2RKF1002X" 0402L#2 2717.63,2271.79 r180 bottom
R183 "ERJ-2RKF1002X" 0402L#2 2717.63,2221.79 r0 bottom
R184 "ERJ-2RKF1002X" 0402L#2 2717.63,2171.79 r0 bottom
R185 "ERJ-2RKF1002X" 0402L#2 2717.63,2121.79 r0 bottom
R186 "ERJ-2RKF1002X" 0402L#2 574.28,1724.12 r270 top
R187 "ERJ-2RKF1002X" 0402L#2 540.28,1724.12 r270 top
R188 "ERJ-2RKF1002X" 0402L#2 1989.17,1035.8 r0 bottom
R189 "ERJ-2RKF1002X" 0402L#2 1989.17,975.8 r0 bottom
R190 "ERJ-2RKF1002X" 0402L#2 1989.17,915.8 r0 bottom
R191 "ERJ-3EKF3300V" 0603L#2 4241.78,83.76 r270 bottom
R192 "ERJ-2RKF1002X" 0402L#2 1586.35,270.54 r270 top
R193 "ERJ-2RKF1002X" 0402L#2 1663.37,268.85 r270 top
R194 "ERJ-2GE0R00X" 0402L#2 1617.34,104.19 r0 bottom
SW1 "500ASSP1M2QE" 500ASSP1M2QE 1167.71,294.89 r270 top
SW2 "cmp00353" 450301014042 82.96,1726.62 r270 top
SW3 "FSMSM" FSMSM 1656.51,134.36 r180 top
SW4 "cmp00353" 450301014042 82.96,1251.62 r270 top
T1 "TCBT-123+" TCBT123 3384.37,848.59 r270 top
T2 "MTX2-183+" DG3006 3207.6,385.26 r180 top
T3 "TCBT-123+" TCBT123 3157.6,848.59 r270 top
T4 "TCBT-123+" TCBT123 3257.6,1866.99 r90 top
T5 "TCBT-123+" TCBT123 3030.83,1866.99 r90 top
T6 "MTX2-183+" DG3006 3207.6,2330.32 r0 top
T7 "TCM2-63WX+" "DB1627 No Vias" 3360,386.83 r0 bottom
T8 "TCM2-63WX+" "DB1627 No Vias" 3358.16,2328.74 r180 bottom
T9 "MTX2-133+" DG3006 2814.69,1200.31 r90 top
TP1 "5011" Keystone5011 736.23,2556.02 r0 top
TP2 "5011" Keystone5011 3980,197.51 r0 top
TP3 "5011" Keystone5011 4060,2546.95 r0 top
TP4 "5010" Keystone5010 584.9,661.2 r0 top
TP5 "5125" Keystone5125 403.94,162.71 r90 top
U1 "DAC39RF12ACK" ACK0256A 3365.08,1357.79 r180 top locked
U2 "TPS259261DRC" DRC0010J 1355.12,320.32 r0 bottom
U3 "TPS7A2501DRVR" DRV0006A 228.97,1662.04 r90 bottom
U4 "TPS7A2501DRVR" DRV0006A 228.97,1312.04 r90 bottom
U5 "SN74AVC4T774RSV" RSV0016A 954.6,1804.59 r270 top
U6 "TPSM82913RDUR" RDU0028A 1114.3,2447.32 r90 top
U7 "24LC64FT-I/MNY" TDFN8#1 1462.28,2300.42 r180 bottom
U8 "TPSM82913RDUR" RDU0028A 299.95,867.68 r90 top
U9 "INA226AIDGS" DGS0010 1178.58,1181.17 r270 bottom
U10 "TPS7A9601DSC" DRC0010J 916.99,1118.46 r0 top
U11 "LM27762DSS" DSS0012B 1101.94,1604.63 r180 top
U12 "SN74AUP1G04DCK" DCK0005A 1047.25,1482.6 r180 top
U13 "LM27762DSS" DSS0012B 1611.36,1717.81 r0 top
U14 "INA226AIDGS" DGS0010 1275.08,661.21 r270 bottom
U15 "TPS7A9601DSC" DRC0010J 1013.49,658.46 r0 top
U16 "INA226AIDGS" DGS0010 1275.08,911.21 r270 bottom
U17 "TPS7A9601DSC" DRC0010J 1013.49,908.46 r0 top
U18 "TPS543620RPYR" RPY0014A 1441.23,2031.18 r0 top
U19 "INA226AIDGS" DGS0010 1933.07,1966.79 r270 bottom
U20 "SN74AVCH2T45DCU" DCU0008A 541.24,1166.86 r270 top
U21 "SN74AVC4T774RSV" RSV0016A 1217.21,2189.08 r0 bottom
U22 "LMK04828BISQ/NOPB" NKD0064A 2376.47,2026.75 r180 top
U23 "TMUX1136DGS" DQA0010A#1 4686.25,247.98 r0 top
U24 "FT4232HL-REEL" LQFP64-MFG 647.64,2155.48 r0 top locked
U25 "SN74LVC1G125DRL" DRL0005A 661.99,2088.55 r0 bottom
U26 "TMUX1136DQA" DQA0010A#2 780.95,2153.25 r0 bottom
U27 "SN74LVC1G125DRL" DRL0005A 661.99,2178.57 r0 bottom
U28 "93LC46B-I/ST" TSSOP-8 553.16,2159.42 r270 bottom
U29 "SN74AVC4T774RSV" RSV0016A 896.08,1528.54 r0 bottom
U30 "SN74CBTLV3257DGV" DGV0016A 722.41,1535.23 r270 top
U31 "SN74AVC4T774RSV" RSV0016A 758.08,1512.79 r180 bottom
U32 "SN74LVC1G125DRL" DRL0005A 492.25,1518.3 r90 bottom
U33 "SN74LVC1G126DRL" DRL0005A 4165.87,131 r0 bottom
U34 "SN74LVC1G11DCKR" DCK0006A 1637.78,253.63 r90 bottom
U35 "SN74LVC1G125DRL" DRL0005A 572.25,1518.3 r270 bottom
U36 "SN74CBTLV3257DGV" DGV0016A 562.41,1535.23 r90 top
U37 "SN74AVC4T774RSV" RSV0016A 510.95,1786.42 r270 bottom
U38 "TPS3125G15DBVR" DBV0005A 1755.73,307.43 r270 bottom
U39 "SN74AVC4T774RSV" RSV0016A 2087.94,1219.42 r0 bottom
U40 "24LC64FT-I/MNY" TDFN8#2 4883.43,244.04 r180 top
Y1 "ABM3-12.000MHZ-D2Y-T" XTAL_ABM3 361.34,2459.89 r45 top
ZZ1 "These assemblies are ESD sensitive, ESD precautions shall be observed." AssemblyNote 100.51,13060.05 r0 top

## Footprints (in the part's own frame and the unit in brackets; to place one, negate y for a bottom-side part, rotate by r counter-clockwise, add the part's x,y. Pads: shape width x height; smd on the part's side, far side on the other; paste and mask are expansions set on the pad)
0201#1 [mm] "Data from Kemet datasheet CC101_COM dated 7/28/11"
  rect 0.36x0.32 smd mask+0: 1(-0.28,0) 2(0.28,0)
0201#2 [mm] "Data from Kemet datasheet CC101_COM dated 7/28/11"
  rect 0.36x0.32 smd mask+0.048: 1(-0.28,0) 2(0.28,0)
0201#3 [mm] "Data from Kemet datasheet CC101_COM dated 7/28/11"
  rrect20% 0.36x0.32 smd mask+0: 1(-0.28,0) 2(0.28,0)
0201_cap#1 [mm] "Data from Kemet datasheet CC101_COM dated 7/28/11"
  rect 0.36x0.32 smd mask+0: 1(-0.28,0) 2(0.28,0)
0201_cap#2 [mm] "Data from Kemet datasheet CC101_COM dated 7/28/11"
  rect 0.36x0.32 smd mask+0.048: 1(-0.28,0) 2(0.28,0)
0201_cap#3 [mm] "Data from Kemet datasheet CC101_COM dated 7/28/11"
  rrect20% 0.36x0.32 smd mask+0: 1(-0.28,0) 2(0.28,0)
0402L#1 [mm] "0402 from SM-752 data"
  rect 0.6x0.5 smd: 1(-0.5,0) 2(0.5,0)
0402L#2 [mm] "0402 from SM-752 data"
  rrect20% 0.6x0.5 smd mask+0: 1(-0.5,0) 2(0.5,0)
0402L_cap [mm] "0402 from SM-752 data"
  rect 0.6x0.5 smd: 1(-0.5,0) 2(0.5,0)
500ASSP1M2QE [mm]
  rect 1.635x1.635 hole 1.09: 1(-2.54,0)
  round 1.635 hole 1.09: 2(0,0) 3(2.54,0)
  silkscreen extent -5.08,-2.54 5.08,2.54
0603L#1 [mm] "0603 from SM-752 data"
  rect 0.8x0.85 smd: 1(-0.7,0) 2(0.7,0)
  silkscreen extent -0.07,-0.33 0.07,0.33
0603L#2 [mm] "0603 from SM-752 data"
  rrect20% 0.8x0.85 smd: 1(-0.7,0) 2(0.7,0)
  silkscreen extent -0.07,-0.33 0.07,0.33
0603L_cap#1 [mm] "0603 from SM-752 data"
  rect 0.8x0.85 smd: 1(-0.7,0) 2(0.7,0)
  silkscreen extent -0.07,-0.33 0.07,0.33
0603L_cap#2 [mm] "0603 from SM-752 data"
  rrect20% 0.8x0.85 smd: 1(-0.7,0) 2(0.7,0)
  silkscreen extent -0.07,-0.33 0.07,0.33
0805L#1 [mm] "0805 from SM-752 data"
  rrect20% 1.1x1.4 smd: 1(-0.75,0) 2(0.75,0)
0805L#2 [mm] "0805 from SM-752 data"
  rect 1.1x1.4 smd: 1(-0.75,0) 2(0.75,0)
0805L_cap [mm] "0805 from SM-752 data"
  rect 1.1x1.4 smd: 1(-0.75,0) 2(0.75,0)
1206L [mm] "1206 from SM-752 data"
  rect 1.1x1.75 smd: 1(-1.35,0) 2(1.35,0)
  silkscreen extent -0.4,-0.77 0.4,0.77
1210L_cap [mm] "1210 from SM-752 data"
  rect 1.1x2.6 smd: 1(-1.35,0) 2(1.35,0)
  silkscreen extent -0.4,-1.2 0.4,1.2
450301014042 [mm]
  round 1.65 hole 1.016: 1(0,0) 2(-2.54,0)
  rect 1.65x1.65 hole 1.016: 3(2.54,0)
  silkscreen extent -4.25,-1.3 4.25,1.3
ACK0256A [mm]
  round 0.5 smd paste+0 mask+0: A1(-7.5,7.5) A2(-6.5,7.5) A3(-5.5,7.5) A4(-4.5,7.5) A5(-3.5,7.5) A6(-2.5,7.5) A7(-1.5,7.5) A8(-0.5,7.5) A9(0.5,7.5) A10(1.5,7.5) A11(2.5,7.5) A12(3.5,7.5) A13(4.5,7.5) A14(5.5,7.5) A15(6.5,7.5) A16(7.5,7.5) B1(-7.5,6.5) B2(-6.5,6.5) B3(-5.5,6.5) B4(-4.5,6.5) B5(-3.5,6.5) B6(-2.5,6.5) B7(-1.5,6.5) B8(-0.5,6.5) B9(0.5,6.5) B10(1.5,6.5) B11(2.5,6.5) B12(3.5,6.5) B13(4.5,6.5) B14(5.5,6.5) B15(6.5,6.5) B16(7.5,6.5) C1(-7.5,5.5) C2(-6.5,5.5) C3(-5.5,5.5) C4(-4.5,5.5) C5(-3.5,5.5) C6(-2.5,5.5) C7(-1.5,5.5) C8(-0.5,5.5) C9(0.5,5.5) C10(1.5,5.5) C11(2.5,5.5) C12(3.5,5.5) C13(4.5,5.5) C14(5.5,5.5) C15(6.5,5.5) C16(7.5,5.5) D1(-7.5,4.5) D2(-6.5,4.5) D3(-5.5,4.5) D4(-4.5,4.5) D5(-3.5,4.5) D6(-2.5,4.5) D7(-1.5,4.5) D8(-0.5,4.5) D9(0.5,4.5) D10(1.5,4.5) D11(2.5,4.5) D12(3.5,4.5) D13(4.5,4.5) D14(5.5,4.5) D15(6.5,4.5) D16(7.5,4.5) E1(-7.5,3.5) E2(-6.5,3.5) E3(-5.5,3.5) E4(-4.5,3.5) E5(-3.5,3.5) E6(-2.5,3.5) E7(-1.5,3.5) E8(-0.5,3.5) E9(0.5,3.5) E10(1.5,3.5) E11(2.5,3.5) E12(3.5,3.5) E13(4.5,3.5) E14(5.5,3.5) E15(6.5,3.5) E16(7.5,3.5) F1(-7.5,2.5) F2(-6.5,2.5) F3(-5.5,2.5) F4(-4.5,2.5) F5(-3.5,2.5) F6(-2.5,2.5) F7(-1.5,2.5) F8(-0.5,2.5) F9(0.5,2.5) F10(1.5,2.5) F11(2.5,2.5) F12(3.5,2.5) F13(4.5,2.5) F14(5.5,2.5) F15(6.5,2.5) F16(7.5,2.5) G1(-7.5,1.5) G2(-6.5,1.5) G3(-5.5,1.5) G4(-4.5,1.5) G5(-3.5,1.5) G6(-2.5,1.5) G7(-1.5,1.5) G8(-0.5,1.5) G9(0.5,1.5) G10(1.5,1.5) G11(2.5,1.5) G12(3.5,1.5) G13(4.5,1.5) G14(5.5,1.5) G15(6.5,1.5) G16(7.5,1.5) H1(-7.5,0.5) H2(-6.5,0.5) H3(-5.5,0.5) H4(-4.5,0.5) H5(-3.5,0.5) H6(-2.5,0.5) H7(-1.5,0.5) H8(-0.5,0.5) H9(0.5,0.5) H10(1.5,0.5) H11(2.5,0.5) H12(3.5,0.5) H13(4.5,0.5) H14(5.5,0.5) H15(6.5,0.5) H16(7.5,0.5) J1(-7.5,-0.5) J2(-6.5,-0.5) J3(-5.5,-0.5) J4(-4.5,-0.5) J5(-3.5,-0.5) J6(-2.5,-0.5) J7(-1.5,-0.5) J8(-0.5,-0.5) J9(0.5,-0.5) J10(1.5,-0.5) J11(2.5,-0.5) J12(3.5,-0.5) J13(4.5,-0.5) J14(5.5,-0.5) J15(6.5,-0.5) J16(7.5,-0.5) K1(-7.5,-1.5) K2(-6.5,-1.5) K3(-5.5,-1.5) K4(-4.5,-1.5) K5(-3.5,-1.5) K6(-2.5,-1.5) K7(-1.5,-1.5) K8(-0.5,-1.5) K9(0.5,-1.5) K10(1.5,-1.5) K11(2.5,-1.5) K12(3.5,-1.5) K13(4.5,-1.5) K14(5.5,-1.5) K15(6.5,-1.5) K16(7.5,-1.5) L1(-7.5,-2.5) L2(-6.5,-2.5) L3(-5.5,-2.5) L4(-4.5,-2.5) L5(-3.5,-2.5) L6(-2.5,-2.5) L7(-1.5,-2.5) L8(-0.5,-2.5) L9(0.5,-2.5) L10(1.5,-2.5) L11(2.5,-2.5) L12(3.5,-2.5) L13(4.5,-2.5) L14(5.5,-2.5) L15(6.5,-2.5) L16(7.5,-2.5) M1(-7.5,-3.5) M2(-6.5,-3.5) M3(-5.5,-3.5) M4(-4.5,-3.5) M5(-3.5,-3.5) M6(-2.5,-3.5) M7(-1.5,-3.5) M8(-0.5,-3.5) M9(0.5,-3.5) M10(1.5,-3.5) M11(2.5,-3.5) M12(3.5,-3.5) M13(4.5,-3.5) M14(5.5,-3.5) M15(6.5,-3.5) M16(7.5,-3.5) N1(-7.5,-4.5) N2(-6.5,-4.5) N3(-5.5,-4.5) N4(-4.5,-4.5) N5(-3.5,-4.5) N6(-2.5,-4.5) N7(-1.5,-4.5) N8(-0.5,-4.5) N9(0.5,-4.5) N10(1.5,-4.5) N11(2.5,-4.5) N12(3.5,-4.5) N13(4.5,-4.5) N14(5.5,-4.5) N15(6.5,-4.5) N16(7.5,-4.5) P1(-7.5,-5.5) P2(-6.5,-5.5) P3(-5.5,-5.5) P4(-4.5,-5.5) P5(-3.5,-5.5) P6(-2.5,-5.5) P7(-1.5,-5.5) P8(-0.5,-5.5) P9(0.5,-5.5) P10(1.5,-5.5) P11(2.5,-5.5) P12(3.5,-5.5) P13(4.5,-5.5) P14(5.5,-5.5) P15(6.5,-5.5) P16(7.5,-5.5) R1(-7.5,-6.5) R2(-6.5,-6.5) R3(-5.5,-6.5) R4(-4.5,-6.5) R5(-3.5,-6.5) R6(-2.5,-6.5) R7(-1.5,-6.5) R8(-0.5,-6.5) R9(0.5,-6.5) R10(1.5,-6.5) R11(2.5,-6.5) R12(3.5,-6.5) R13(4.5,-6.5) R14(5.5,-6.5) R15(6.5,-6.5) R16(7.5,-6.5) T1(-7.5,-7.5) T2(-6.5,-7.5) T3(-5.5,-7.5) T4(-4.5,-7.5) T5(-3.5,-7.5) T6(-2.5,-7.5) T7(-1.5,-7.5) T8(-0.5,-7.5) T9(0.5,-7.5) T10(1.5,-7.5) T11(2.5,-7.5) T12(3.5,-7.5) T13(4.5,-7.5) T14(5.5,-7.5) T15(6.5,-7.5) T16(7.5,-7.5)
  silkscreen extent -9.25,-8.6 8.6,8.6
AssemblyNote [mil] "Assembly Note"
Balun-Shield [mm]
  round 0.4 hole 2.134 mask+0: 1(-6.453,0.144)
  silkscreen extent -8.1,-4.83 4.83,4.83
CCS0603FLxLxx [mm]
  rrect33% 1.41x0.92 smd: 1(-0.9,0) 2(0.89,0)
CE_Mark_5mm [mil] "Minimum text height for CE Mark"
"DAC39 - ATS-54170R-C1-R0_BGA_HEATSINK_17p0x17p0mm" [mil]
"DAC39R - F17HA-05HC_FAN_17p0x17p0mm" [mil]
"DB1627 No Vias" [mm]
  rrect10% 0.76x1.65 smd: 1(-1.27,1.59) 2(0,1.59) 3(1.27,1.59) 4(1.27,-1.59) 5(0,-1.59) 6(-1.27,-1.59)
  silkscreen extent -1.91,-1.91 1.91,3.09
DBV0005A [mm] "SOT23, 5-Leads, Body 2.9x1.6mm, Pitch 0.95mm, Lead Span 2.8mm, IPC High Density"
  rrect18% 1.1x0.6 smd mask+0: 1(-1.3,0.95) 2(-1.3,0) 3(-1.3,-0.95) 4(1.3,-0.95) 5(1.3,0.95)
  silkscreen extent -0.35,-1.55 0.35,1.55
DCK0005A [mm] "SOT353, 5-Leads, Body 2x1.3mm, Pitch 0.65mm, Lead Span 2.1mm, IPC High Density"
  rrect25% 0.9x0.4 smd mask+0: 1(-1.1,0.65) 2(-1.1,0) 3(-1.1,-0.65) 4(1.1,-0.65) 5(1.1,0.65)
  silkscreen extent -0.25,-1.1 0.25,1.1
DCK0006A [mm] "SOT23, 6-Leads, Body 2x1.3mm, Pitch 0.65mm, Lead Span 2.1mm, IPC High Density"
  rrect25% 0.9x0.4 smd mask+0: 1(-1.1,0.65) 2(-1.1,0) 3(-1.1,-0.65) 4(1.1,-0.65) 5(1.1,0) 6(1.1,0.65)
  silkscreen extent -1.3,-1.07 0.55,1.1
DCU0008A [mm] "TSSOP, 8-Leads, Body 2x2.3mm, Pitch 0.5mm, IPC High Density"
  rrect30% 0.8x0.3 smd mask+0: 1(-1.55,0.75) 2(-1.55,0.25) 3(-1.55,-0.25) 4(-1.55,-0.75) 5(1.55,-0.75) 6(1.55,-0.25) 7(1.55,0.25) 8(1.55,0.75)
  silkscreen extent -1.05,-1.05 0.38,1.05
DG3006 [mm]
  rrect50% 0.3x1 smd mask+0: 1(-0.65,-1.55) 2(0,-1.55) 3(0.65,-1.55) 7(0.65,1.55) 8(0,1.55) 9(-0.65,1.55)
  rrect50% 1x0.3 smd mask+0: 4(2.05,-0.65) 5(2.05,0) 6(2.05,0.65) 10(-2.05,0.65) 11(-2.05,0) 12(-2.05,-0.65)
  round 0.025 smd paste+0 mask+0.05: " "(0,0)
  silkscreen extent -2,-1.9 2,1.5
DGS0010 [mm] "TSSOP, 10-Leads, Body 3x3mm, Pitch 0.5mm, IPC Medium Density"
  rrect30% 1.45x0.3 smd mask+0: 1(-2.2,1) 2(-2.2,0.5) 3(-2.2,0) 4(-2.2,-0.5) 5(-2.2,-1) 6(2.2,-1) 7(2.2,-0.5) 8(2.2,0) 9(2.2,0.5) 10(2.2,1)
  silkscreen extent -2.75,-1.55 0.9,1.55
DGV0016A [mm] "TSSOP, 16-Leads, Body 3.6x4.4mm, Pitch 0.4mm, IPC High Density"
  rrect30% 1.2x0.225 smd mask+0: 1(-2.85,1.4) 2(-2.85,1) 3(-2.85,0.6) 4(-2.85,0.2) 5(-2.85,-0.2) 6(-2.85,-0.6) 7(-2.85,-1) 8(-2.85,-1.4) 9(2.85,-1.4) 10(2.85,-1) 11(2.85,-0.6) 12(2.85,-0.2) 13(2.85,0.2) 14(2.85,0.6) 15(2.85,1) 16(2.85,1.4)
  silkscreen extent -3.32,-1.85 1.85,1.85
DQA0010A#1 [mm] "SON, 10-Leads, Body 1x2.5mm, Pitch 0.5mm, TI Recommended"
  rrect50% 0.565x0.2 smd mask+0: 1(-0.417,1) 2(-0.417,0.5) 4(-0.417,-0.5) 5(-0.417,-1) 6(0.417,-1) 7(0.417,-0.5) 9(0.417,0.5) 10(0.417,1)
  rrect28% 0.565x0.36 on Top Paste mask+0: 3(-0.417,0) 8(0.417,0)
  rrect25% 0.565x0.4 smd paste-0.2 mask+0: 3(-0.417,0) 8(0.417,0)
  silkscreen extent -0.67,-1.45 0.55,1.45
DQA0010A#2 [mm] "SON, 10-Leads, Body 1x2.5mm, Pitch 0.5mm, TI Recommended"
  rrect50% 0.565x0.2 smd mask+0: 1(-0.417,1) 2(-0.417,0.5) 4(-0.417,-0.5) 5(-0.417,-1) 6(0.417,-1) 7(0.417,-0.5) 9(0.417,0.5) 10(0.417,1)
  rrect28% 0.565x0.36 on Bottom Paste mask+0: 3(-0.417,0) 8(0.417,0)
  rrect25% 0.565x0.4 smd paste-0.2 mask+0: 3(-0.417,0) 8(0.417,0)
  silkscreen extent -0.67,-1.45 0.55,1.45
DQK0006C [mm] "WSON"
  rrect12% 0.9x0.86 on Bottom Paste: 0(0,0.325)
  rrect34% 0.7x0.29 on Bottom Paste: 0(0.095,-0.65)
  rrect33% 0.45x0.3 smd: 1(-0.975,0.65) 2(-0.975,0) 3(-0.975,-0.65) 4(0.975,-0.65) 5(0.975,0) 6(0.975,0.65)
  rrect33% 0.75x0.3 smd paste-0.15: 7(0.095,-0.65)
  rrect11% 1x0.95 smd paste-0.5: 8(0,0.325)
  silkscreen extent -1.15,-1.15 1.15,1.15
DRC0010J [mm] "VSON-10"
  rrect42% 0.6x0.24 smd mask+0: 1(-1.4,1) 2(-1.4,0.5) 3(-1.4,0) 4(-1.4,-0.5) 5(-1.4,-1) 6(1.4,-1) 7(1.4,-0.5) 8(1.4,0) 9(1.4,0.5) 10(1.4,1)
  round 0.454 hole 0.2 mask+0: 11(-0.575,0) 11(0,-0.95) 11(0,0.95) 11(0.575,0)
  round 0.025 smd paste+0 mask+0.07: " "(0,0)
  silkscreen extent -1.97,0.95 -1.84,1.08
DRL0005A [mm] "SOTFL, 5-Flat Leads, Body 1.2x1.6x0.6mm, Pitch 0.5mm, TI recommended"
  rrect33% 0.67x0.3 smd mask+0: 1(-0.74,0.5) 2(-0.74,0) 3(-0.74,-0.5) 4(0.74,-0.5) 5(0.74,0.5)
  silkscreen extent -0.9,-0.95 0.5,0.95
DRV0006A [mm] "SON, 6-Leads, Body 2x2mm, Pitch 0.65mm, Thermal Pad 1.6x1mm, TI Recommended"
  rrect33% 0.45x0.3 smd mask+0: 1(-0.975,0.65) 2(-0.975,0) 3(-0.975,-0.65) 4(0.975,-0.65) 5(0.975,0) 6(0.975,0.65)
  round 0.454 hole 0.2 mask+0: 7(0,-0.55) 7(0,0.55)
  rrect14% 1x0.7 on Bottom Paste: 7(0,-0.45) 7(0,0.45)
  rrect10% 1x1.6 smd paste-0.5 mask+0: 7(0,0)
  silkscreen extent -1.05,-1.2 1.05,1.2
DSS0012B [mm] "WSON-10"
  rrect40% 0.5x0.25 smd mask+0: 1(-0.95,1.25) 2(-0.95,0.75) 3(-0.95,0.25) 4(-0.95,-0.25) 5(-0.95,-0.75) 6(-0.95,-1.25) 7(0.95,-1.25) 8(0.95,-0.75) 9(0.95,-0.25) 10(0.95,0.25) 11(0.95,0.75) 12(0.95,1.25)
  round 0.454 hole 0.2 mask+0: 13(0,1.075) 13(0,-1.075) 13(0,0)
  rrect11% 1x2.65 smd paste-0.5 mask+0: 13(0,0)
  silkscreen extent -1.3,1.63 -1.24,1.68
ESD_Overlay_Small [mil]
  silkscreen extent -62,-48 64,61
FCC_disclaimer_stacked [mil]
FDL_Small [mil]
  silkscreen extent -54,-32 54,73
Fiducial10-20 [mm]
  round 1 smd mask+0: 1(0,0)
FIL_BNX002-11 [mm]
  rect 1.8x1.8 hole 1.2: 1(2.5,2.5)
  round 1.8 hole 1.2: 2(2.5,-2.5) 3(-2.5,2.5) 4(-2.5,-2.5) 4(0,0) 4(5,0)
  silkscreen extent -6,-5.5 6,6.35
FP-2116-440-AL_STANDOFF_HEX_1-4-MFG [mm]
  round 3.2 hole 3.2 unplated paste+0 mask+0: ""(0,0)
FP-132134-15_CONN_SMA_JACK-MFG#1 [mm]
  round 0.914 smd paste+0 mask+0: 1(0,0)
  round 2.6 hole 1.7 paste+0 mask+0: 2(-2.54,2.54) 3(2.54,2.54) 4(-2.54,-2.54) 5(2.54,-2.54)
  silkscreen extent -3.6,-3.6 3.6,3.6
FP-132134-15_CONN_SMA_JACK-MFG#2 [mm]
  round 0.864 smd paste+0 mask+0: 1(0,0)
  round 2.6 hole 1.7 paste+0 mask+0: 2(-2.54,2.54) 3(2.54,2.54) 4(-2.54,-2.54) 5(2.54,-2.54)
  silkscreen extent -3.6,-3.6 3.6,3.6
FSMSM [mm]
  rrect10% 2.2x1.6 smd: 1(-4.6,0) 2(4.6,0)
HiRose-HK-LR-SR2-SWM1092-04A-MicroStirp-6mil-Female-Backdrill [mil]
  round 22 hole 12 mask+0: 2(11,-25) 3(11,25)
  round 24 hole 12 mask+0: 2(51,-33) 2(91,-33) 3(51,33) 3(91,33) 3(131,-33) 3(131,33) 3(171,-33) 3(171,33)
  round 81 hole 81 mask+0: 2(110,-187.5) 3(110,187.5)
  round 66.93 hole 66.93 mask+0: 4(87,-98.5) 4(87,98.5)
  round 1 smd paste-100 mask+1.97: " "(75,0)
  round 1 on Mid1 mask+0: " "(86.25,0)
  round 1 smd paste+0 mask+1.97: " "(93.75,131.66) " "(93.75,-131.66)
Hirose_UX60SC-MB-5S8 [mm] "Connector, Receptacle, Mini-USB Type B, R/A, SMT"
  rrect30% 1.4x0.5 smd: 1(6.1,1.6) 2(6.1,0.8) 3(6.1,0) 4(6.1,-0.8) 5(6.1,-1.6)
  oval 3.6x1.1 hole 0.7 slot 3.2 at 0 deg: S1(3.7,3.65) S2(3.7,-3.65)
  silkscreen extent 0.15,-3.85 6.75,3.85
IEC_HotSurface_Small [mil]
  silkscreen extent -107,-93 107,92
Keystone5010 [mil] "Keystone Multipurpose loops"
  round 87 hole 63: 1(0,0)
  silkscreen extent -70,-70 70,70
Keystone5011 [mil] "Keystone Multipurpose loops"
  round 87 hole 63: 1(0,0)
  silkscreen extent -70,-70 70,70
Keystone5125 [mil] "Keystone Multipurpose loops"
  round 87 hole 63: 1(0,0)
  silkscreen extent -70,-70 70,70
Label_650x200 [mil] "Thermal Transfer Label"
  round 1 on Mech13: 0(0,0)
  silkscreen extent -325,-100 325,100
LED_LTST-C190-Green [mm] "Lite-On"
  rect 0.8x0.8 smd: 1(-0.75,0) 2(0.75,0)
  silkscreen extent -1.1,-0.8 1.8,0.8
LQFP64-MFG [mm]
  rrect33% 1.65x0.3 smd paste+0 mask+0: 1(-5.575,3.75)
  rrect100% 1.65x0.3 smd paste+0 mask+0: 2(-5.575,3.25) 3(-5.575,2.75) 4(-5.575,2.25) 5(-5.575,1.75) 6(-5.575,1.25) 7(-5.575,0.75) 8(-5.575,0.25) 9(-5.575,-0.25) 10(-5.575,-0.75) 11(-5.575,-1.25) 12(-5.575,-1.75) 13(-5.575,-2.25) 14(-5.575,-2.75) 15(-5.575,-3.25) 16(-5.575,-3.75) 33(5.575,-3.75) 34(5.575,-3.25) 35(5.575,-2.75) 36(5.575,-2.25) 37(5.575,-1.75) 38(5.575,-1.25) 39(5.575,-0.75) 40(5.575,-0.25) 41(5.575,0.25) 42(5.575,0.75) 43(5.575,1.25) 44(5.575,1.75) 45(5.575,2.25) 46(5.575,2.75) 47(5.575,3.25) 48(5.575,3.75)
  rrect100% 0.3x1.65 smd paste+0 mask+0: 17(-3.75,-5.575) 18(-3.25,-5.575) 19(-2.75,-5.575) 20(-2.25,-5.575) 21(-1.75,-5.575) 22(-1.25,-5.575) 23(-0.75,-5.575) 24(-0.25,-5.575) 25(0.25,-5.575) 26(0.75,-5.575) 27(1.25,-5.575) 28(1.75,-5.575) 29(2.25,-5.575) 30(2.75,-5.575) 31(3.25,-5.575) 32(3.75,-5.575) 49(3.75,5.575) 50(3.25,5.575) 51(2.75,5.575) 52(2.25,5.575) 53(1.75,5.575) 54(1.25,5.575) 55(0.75,5.575) 56(0.25,5.575) 57(-0.25,5.575) 58(-0.75,5.575) 59(-1.25,5.575) 60(-1.75,5.575) 61(-2.25,5.575) 62(-2.75,5.575) 63(-3.25,5.575) 64(-3.75,5.575)
  silkscreen extent -7.12,-5.05 5.05,5.05
Molex_0853050232 [mm] "Plug, 50 Ohm, Straight, SMT"
  rrect17% 0.6x1.3 smd: 1(0,0)
  round 0.654 hole 0.4 mask+0: 2(-2.3,-3.95) 2(-2.3,-2.15) 2(-1.4,-5.25) 2(-1.4,-0.85) 2(1.4,-5.25) 2(1.4,-0.85) 2(2.3,-3.95) 2(2.3,-2.15)
  round 0.025 smd paste+0 mask+0.05: " "(0,-5.35)
NFM15PC [mm] "SMD, 3-Leads, Body 1x0.5mm"
  rrect10% 0.3x0.3 smd mask+0: 1(-0.5,0) 3(0.5,0)
  rrect10% 0.25x0.25 smd mask+0: 2(0,0.25) 2(0,-0.25)
NFM18PC [mm]
  rrect20% 0.6x0.6 smd mask+0: 1(-0.8,0) 3(0.8,0)
  rrect20% 0.4x0.4 smd mask+0: 2(0,-0.4) 2(0,0.4)
NFM31PC#1 [mm]
  rrect10% 0.95x1.2 smd paste+0: 1(-1.675,0) 3(1.675,0)
  round 0.2 / inner round 0.454 / far side round 0.454 hole 0.2 mask+0: 2(-0.305,-1.105) 2(-0.305,1.105) 2(0.305,-1.105) 2(0.305,1.105)
  rrect10% 1x1 smd paste+0: 2(0,-0.8) 2(0,0.8)
NFM31PC#2 [mm]
  rrect10% 0.95x1.2 smd paste+0: 1(-1.675,0) 3(1.675,0)
  round 0.2 / inner round 0.454 / far side round 0.454 hole 0.2 mask+0: 2(-0.305,-1.054) 2(-0.305,1.105) 2(0.305,-1.054) 2(0.305,1.105)
  rrect10% 1x1 smd paste+0: 2(0,-0.8) 2(0,0.8)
